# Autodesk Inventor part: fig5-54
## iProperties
Created: 2007-01
Part Number: fig5-54
Document SubType Name: Modeling
Designer: Administrator
Density: 1 g/cm^3
Author: Administrator
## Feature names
1. Extrusion1
2. Extrusion2
3. Extrusion3
